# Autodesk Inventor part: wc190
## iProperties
Shininess: 64.0
Length Units: 11272
Angle Units: 11279
Time Units: 11290
Mass Units: 11286
Length Display Precision: 3
Angle Display Precision: 2
Compacted: True
Part Number: wc190
Document SubType Name: Modeling
Created: 2004-08
Designer: John Blackburn
Manufacturer: Standard
Standards Organization: Custom
Density: 0.0
Volumn: 0.0
Area: 0.0
PropertySet Name: Model Information
Control State: 0
Master: False
Checked Out: False
Author: John Blackburn
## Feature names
1. Base1
